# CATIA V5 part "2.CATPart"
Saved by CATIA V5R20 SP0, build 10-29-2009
Part number: 2
Bounding box of the stored display mesh (mm): x -211 to 75, y -244.182 to 244.182, z -10 to 197.745
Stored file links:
  E:\Ehsan\Amoozesh\CATIA\CATIA Course\Advanced\Videos\Session-22\2.CATPart
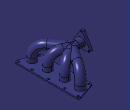
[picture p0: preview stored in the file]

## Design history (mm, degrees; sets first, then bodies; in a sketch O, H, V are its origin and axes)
AxisSystem1: origin (0, 0, 0), X (1, 0, 0), Y (0, 1, 0), Z (0, 0, 1)
Set1
  Point1: (-191, 0, 121), in AxisSystem1
  Point2: (-121, 0, 121), in AxisSystem1
  Point3: (0, -185, 115), in AxisSystem1
  Point4: (0, -185, 0), in AxisSystem1
  Line1: type PtPt, FirstPoint Point1, SecondPoint Point2
  Line2: type PtPt, FirstPoint Point2, SecondPoint Point3
  Line3: type PtPt, FirstPoint Point3, SecondPoint Point4
  Corner1: Element1 Line1, Element2 Line2, Radius 50
  Corner2 "Corner.2": Element1 Corner1, Element2 Line3, Radius 85
  Point5: (0, -65, 0), in AxisSystem1
  Point6: (0, -65, 115), in AxisSystem1
  Line4: type PtPt, FirstPoint Point5, SecondPoint Point6
  Line5: type PtPt, FirstPoint Point6, SecondPoint Point2
  Line6: type PtPt, FirstPoint Point2, SecondPoint Point1
  Corner3: Element1 Line4, Element2 Line5, Radius 85
  Corner4: Element1 Corner3, Element2 Line6, Radius 60
  MultiSel1
  Sweep1: type Circle, Guide Corner2, Radius 30
  Plane1: type OffsetPt, RefPlane YZ plane of AxisSystem1, RefPoint vertex of Line1
  Sketch1 on Plane1, origin (-191, 0, 0), H (0, 1, 0), V (0, 0, 1)
    circle A1 centre (0, 121) radius 30
    point P1 (0, 121)
    reference projected point E1 (0, 121) from vertex of Line1
    radius A1 = 30
    coincidence: P1 V
    concentricity: A1 E1
  Sweep2: type Circle, Guide Corner2, Radius 30
  Sweep3: type Circle, Guide Corner4, Radius 30
  Sweep4: type Circle, Guide {symmetry ToTransfor Corner4, Reference ZX plane of AxisSystem1}, Radius 30
  Sweep5: type Circle, Guide {symmetry ToTransfor Corner2, Reference ZX plane of AxisSystem1}, Radius 30
  Add1: tool Sweep3
  Add2: tool Sweep4
  Add3: tool Sweep5
  Shell1: IntOffset 1, Face (face of Sweep2; face of Sweep3; face of Sweep4; face of Sweep5; face of Sweep5), ExtOffset 1
  Sketch2 on face of Sweep5, origin (-191, 0, 0), H (0, -1, 0), V (0, 0, 1)
    projected circle E1 centre (0, 121) radius 29 from edge [face of Shell1 | face of Sweep5]
    point P1 (0, 207.6274)
    line L1 (-8.6603, 192.7452) -> (-66.4633, 92.6274)
    line L2 (-57.803, 77.6274) -> (57.803, 77.6274)
    line L3 (66.4633, 92.6274) -> (8.6603, 192.7452)
    point P2 (0, 121)
    arc A1 centre (-57.803, 87.6274) radius 10 from (-66.4633, 92.6274) to (-57.803, 77.6274) ccw
    point P5 (-57.803, 87.6274)
    arc A2 centre (57.803, 87.6274) radius 10 from (57.803, 77.6274) to (66.4633, 92.6274) ccw
    point P8 (57.803, 87.6274)
    arc A3 centre (0, 187.7452) radius 10 from (8.6603, 192.7452) to (-8.6603, 192.7452) ccw
    point P11 (0, 187.7452)
    construction circle A4 centre (0, 121) radius 66.7452
    point P12 (0, 121)
    circle A5 centre (0, 187.7452) radius 5
    circle A6 centre (-57.803, 87.6274) radius 5
    circle A7 centre (57.803, 87.6274) radius 5
    angle L1 L3 = 60
    distance P1 L2 = 130
    radius A1 = 10
    radius A2 = 10 {= Sketch2.radius(A1)}
    radius A3 = 10
    distance P2 P12 = 0
    radius A5 = 5
    horizontal: L2 H
    symmetry: L3 L1 V
    concentricity: P2 E1
    tangency: A1 L1, A1 L2, A2 L2, A2 L3, A3 L3, A3 L1
    coincidence: A4 P5, A4 P8, A4 P11
  Extrude1: Element1 Sketch2, Lim1 20, Lim2 0
  Add4: tool Extrude1
  Sketch3 on face of Sweep4, origin (0, 0, 0), H (0, 1, 0), V (1, 0, 0)
    projected circle E1 centre (-185, 0) radius 29 from edge [face of Shell1 | face of Sweep2]
    projected circle E2 centre (-65, 0) radius 29 from edge [face of Shell1 | face of Sweep3]
    projected circle E3 centre (65, 0) radius 29 from edge [face of Shell1 | face of Sweep4]
    projected circle E4 centre (185, 0) radius 29 from edge [face of Shell1 | face of Sweep5]
    line L1 (250, 75) -> (250, 75)
    line L2 (189.1886, -75) -> (-189.1886, -75)
    line L3 (-229.1886, 75) -> (229.1886, 75)
    point P1 (250, 75)
    point P2 (-250, 75)
    line L4 (243.4189, 55.2566) -> (203.4189, -64.7434)
    point P3 (250, 75)
    point P4 (200, -75)
    point P5 (250, -75)
    point P6 (-200, -75)
    point P7 (-250, 75)
    line L5 (-243.4189, 55.2566) -> (-203.4189, -64.7434)
    arc A1 centre (-229.1886, 60) radius 15 from (-243.4189, 55.2566) to (-229.1886, 75) cw
    arc A2 centre (229.1886, 60) radius 15 from (243.4189, 55.2566) to (229.1886, 75) ccw
    arc A3 centre (189.1886, -60) radius 15 from (203.4189, -64.7434) to (189.1886, -75) cw
    arc A4 centre (-189.1886, -60) radius 15 from (-203.4189, -64.7434) to (-189.1886, -75) ccw
    circle A5 centre (-229.1886, 60) radius 7.5
    circle A6 centre (-189.1886, -60) radius 7.5
    construction line L6 (-125, -48.1985) -> (-125, 55.2566)
    circle A7 centre (-125, -60) radius 7.5
    point P22 (-125, -60)
    circle A8 centre (-125, 60) radius 7.5
    point P23 (-125, 60)
    circle A9 centre (0, 60) radius 7.5
    point P24 (0, 60)
    circle A10 centre (0, -60) radius 7.5
    point P25 (0, -60)
    circle A11 centre (189.1886, -60) radius 7.5
    circle A12 centre (125, -60) radius 7.5
    circle A13 centre (125, 60) radius 7.5
    circle A14 centre (229.1886, 60) radius 7.5
    distance L2 L3 = 150
    distance P3 P5 = 150
    distance P4 P5 = 50
    distance P2 P1 = 500
    radius A1 = 15
    radius A2 = 15
    radius A3 = 15
    radius A4 = 15
    radius A5 = 7.5
    radius A6 = 7.5
    radius A7 = 7.5
    radius A8 = 7.5
    radius A9 = 7.5
    radius A10 = 7.5
    vertical: L1 V
    horizontal: L2 H, L3 H
    equidistance: L2 L3 O
    coincidence: L1 P5, L2 P5, L5 P7, L3 P2, L4 P3, L3 P1, L4 P4, L2 P4, L5 P6, L2 P6, P22 L6, P23 L6, P24 V, P25 V
    symmetry: P4 P6 V, P3 P7 V, L4 L5 V, E2 E1 L6, A6 A11 V, A7 A12 V, A8 A13 V, A5 A14 V
    tangency: A1 L5, A1 L3, A2 L4, A2 L3, A3 L4, A3 L2, A4 L5, A4 L2
  Extrude2: Lim1 10, Lim2 0, Element1 Sketch3
  Add5: tool Add4
Body1 (main body)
